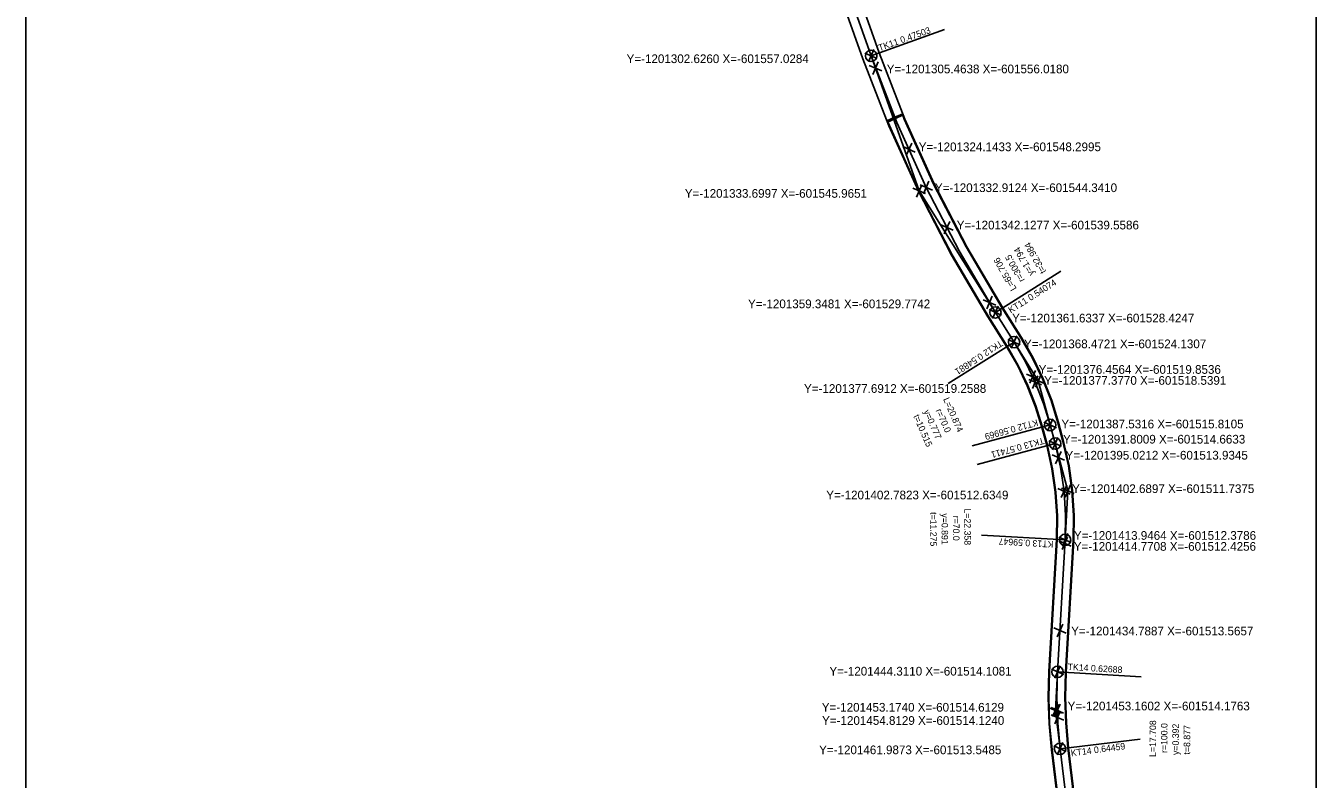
# Model space of a CAD drawing. Extents: x -601752 to -601455, y -1201912 to -1200862.
# Drawn here: x -601751.6 to -601454.6, y -1201469 to -1201295.7 of the extents above; entities that cross this region are included whole.
import ezdxf

# ---------------------------------------------------------------- set-up
doc = ezdxf.new("R2010")
doc.units = 0
for name, color, linetype in [('g_vytyceni oblouky', 7, 'Continuous'), ('g_vytyceni příčné', 7, 'Continuous'), ('u_návrh', 7, 'Continuous'), ('u_oblouky', 7, 'Continuous'), ('u_osa', 7, 'Continuous'), ('u_popis oblouky', 7, 'Continuous'), ('x_rám', 7, 'Continuous')]:
    doc.layers.add(name, color=color, linetype=linetype)

msp = doc.modelspace()

# ---------------------------------------------------------------- linework, layer by layer
at = {"layer": 'g_vytyceni oblouky'}
for p, q in [((-601558.46, -1201301.99), (-601555.6, -1201303.26)), ((-601556.4, -1201301.2), (-601557.66, -1201304.05)), ((-601545.33, -1201332.27), (-601546.6, -1201335.13)), ((-601545.77, -1201332.28), (-601542.91, -1201333.54)), ((-601543.71, -1201331.48), (-601544.97, -1201334.34)), ((-601547.39, -1201333.07), (-601544.54, -1201334.33)), ((-601529.85, -1201361), (-601527, -1201362.27)), ((-601527.79, -1201360.2), (-601529.06, -1201363.06)), ((-601525.56, -1201367.84), (-601522.7, -1201369.1)), ((-601523.5, -1201367.04), (-601524.76, -1201369.9)), ((-601519.97, -1201376.74), (-601517.11, -1201378.01)), ((-601518.63, -1201376.26), (-601519.89, -1201379.12)), ((-601517.91, -1201375.95), (-601519.17, -1201378.81)), ((-601520.69, -1201377.06), (-601517.83, -1201378.32)), ((-601517.24, -1201386.9), (-601514.38, -1201388.16)), ((-601515.18, -1201386.1), (-601516.44, -1201388.96)), ((-601516.09, -1201391.17), (-601513.23, -1201392.43)), ((-601514.03, -1201390.37), (-601515.3, -1201393.23)), ((-601514.06, -1201402.15), (-601511.21, -1201403.41)), ((-601512, -1201401.35), (-601513.27, -1201404.21)), ((-601513.17, -1201402.06), (-601510.31, -1201403.32)), ((-601511.1, -1201401.26), (-601512.37, -1201404.12)), ((-601511.75, -1201412.52), (-601513.01, -1201415.38)), ((-601513.81, -1201413.31), (-601510.95, -1201414.58)), ((-601515.54, -1201443.68), (-601512.68, -1201444.94)), ((-601513.48, -1201442.88), (-601514.74, -1201445.74)), ((-601516.04, -1201452.54), (-601513.18, -1201453.81)), ((-601515.61, -1201452.53), (-601512.75, -1201453.79)), ((-601513.98, -1201451.75), (-601515.25, -1201454.6)), ((-601513.54, -1201451.73), (-601514.81, -1201454.59)), ((-601514.98, -1201461.35), (-601512.12, -1201462.62)), ((-601512.92, -1201460.56), (-601514.18, -1201463.42))]:
    msp.add_line(p, q, dxfattribs=at)
at = {"layer": 'g_vytyceni příčné'}
for p, q in [((-601557.45, -1201304.83), (-601554.59, -1201306.1)), ((-601555.39, -1201304.04), (-601556.65, -1201306.89)), ((-601547.67, -1201322.71), (-601548.93, -1201325.57)), ((-601549.73, -1201323.51), (-601546.87, -1201324.78)), ((-601538.93, -1201340.7), (-601540.19, -1201343.56)), ((-601540.99, -1201341.5), (-601538.13, -1201342.76)), ((-601531.2, -1201358.72), (-601528.35, -1201359.98)), ((-601529.14, -1201357.92), (-601530.41, -1201360.78)), ((-601521.28, -1201375.82), (-601518.42, -1201377.09)), ((-601519.22, -1201375.03), (-601520.49, -1201377.89)), ((-601515.36, -1201394.39), (-601512.51, -1201395.65)), ((-601513.3, -1201393.59), (-601514.57, -1201396.45)), ((-601513.85, -1201414.14), (-601511, -1201415.4)), ((-601511.79, -1201413.34), (-601513.06, -1201416.2)), ((-601514.99, -1201434.16), (-601512.14, -1201435.42)), ((-601512.93, -1201433.36), (-601514.2, -1201436.22)), ((-601513.49, -1201453.38), (-601514.76, -1201456.24)), ((-601515.55, -1201454.18), (-601512.7, -1201455.45))]:
    msp.add_line(p, q, dxfattribs=at)
at = {"layer": 'u_návrh'}
for points in [[(-601563.54, -1201278.37), (-601555.15, -1201301.93), (-601549.25, -1201317.17), (-601542.54, -1201332.04), (-601535.03, -1201346.52), (-601526.72, -1201360.59), (-601522.42, -1201367.44), (-601519.75, -1201372.06), (-601517.42, -1201376.89), (-601515.46, -1201381.89), (-601513.89, -1201386.98), (-601512.72, -1201391.32), (-601511.46, -1201396.89), (-601510.64, -1201402.58), (-601510.28, -1201408.31), (-601510.38, -1201414.02), (-601512.11, -1201444.4), (-601512.27, -1201450.21), (-601512.09, -1201455.99), (-601511.56, -1201461.78), (-601506.35, -1201504.94)], [(-601567.28, -1201279.79), (-601558.9, -1201303.32), (-601552.94, -1201318.72), (-601546.14, -1201333.79), (-601538.53, -1201348.46), (-601530.13, -1201362.67), (-601525.84, -1201369.5), (-601523.29, -1201373.93), (-601521.09, -1201378.49), (-601519.24, -1201383.21), (-601517.73, -1201388.09), (-601516.61, -1201392.28), (-601515.4, -1201397.61), (-601514.63, -1201402.99), (-601514.28, -1201408.41), (-601514.38, -1201413.87), (-601516.11, -1201444.23), (-601516.27, -1201450.21), (-601516.08, -1201456.23), (-601515.54, -1201462.2), (-601510.32, -1201505.38)], [(-601549.72, -1201315.95), (-601551.7, -1201316.84), (-601553.38, -1201317.58)], [(-601549.62, -1201316.23), (-601551.59, -1201317.11), (-601553.27, -1201317.86)], [(-601549.75, -1201316.3), (-601549.39, -1201317.23), (-601542.68, -1201332.11), (-601535.16, -1201346.59), (-601526.84, -1201360.67), (-601522.55, -1201367.52), (-601519.89, -1201372.13), (-601517.56, -1201376.95), (-601515.6, -1201381.93), (-601514.03, -1201387.02), (-601512.87, -1201391.36), (-601511.61, -1201396.91), (-601510.79, -1201402.59), (-601510.43, -1201408.32), (-601510.53, -1201414.01), (-601512.26, -1201444.39), (-601512.42, -1201450.21), (-601512.24, -1201456), (-601511.71, -1201461.79), (-601506.5, -1201504.96), (-601506.06, -1201509.37), (-601505.82, -1201513.81), (-601505.77, -1201518.24), (-601506.19, -1201556.5)], [(-601553.14, -1201317.8), (-601552.81, -1201318.66), (-601546.01, -1201333.72), (-601538.39, -1201348.39), (-601530, -1201362.6), (-601525.72, -1201369.43), (-601523.16, -1201373.86), (-601520.96, -1201378.43), (-601519.1, -1201383.16), (-601517.59, -1201388.04), (-601516.46, -1201392.25), (-601515.25, -1201397.59), (-601514.48, -1201402.97), (-601514.13, -1201408.4), (-601514.23, -1201413.88), (-601515.96, -1201444.23), (-601516.12, -1201450.21), (-601515.93, -1201456.22), (-601515.39, -1201462.18), (-601510.17, -1201505.36), (-601509.75, -1201509.65), (-601509.52, -1201513.93), (-601509.47, -1201518.24), (-601509.71, -1201540.62)]]:
    msp.add_lwpolyline(points, dxfattribs=at)
at = {"layer": 'u_oblouky'}
for p, q in [((-601557.03, -1201302.63), (-601540.12, -1201296.61)), ((-601557.03, -1201302.63), (-601545.97, -1201333.7)), ((-601528.42, -1201361.63), (-601545.97, -1201333.7)), ((-601528.42, -1201361.63), (-601513.35, -1201352.17)), ((-601524.13, -1201368.47), (-601539.32, -1201378.01)), ((-601524.13, -1201368.47), (-601518.54, -1201377.38)), ((-601515.81, -1201387.53), (-601518.54, -1201377.38)), ((-601515.81, -1201387.53), (-601533.79, -1201392.36)), ((-601514.66, -1201391.8), (-601532.62, -1201396.62)), ((-601514.66, -1201391.8), (-601511.74, -1201402.69)), ((-601512.38, -1201413.95), (-601511.74, -1201402.69)), ((-601512.38, -1201413.95), (-601531.6, -1201412.85)), ((-601514.11, -1201444.31), (-601514.61, -1201453.17)), ((-601514.11, -1201444.31), (-601494.9, -1201445.41)), ((-601513.55, -1201461.99), (-601514.61, -1201453.17)), ((-601513.55, -1201461.99), (-601495.1, -1201459.76))]:
    msp.add_line(p, q, dxfattribs=at)
for centre in [(-601557.03, -1201302.63), (-601528.42, -1201361.63), (-601524.13, -1201368.47), (-601515.81, -1201387.53), (-601514.66, -1201391.8), (-601512.38, -1201413.95), (-601514.11, -1201444.31), (-601513.55, -1201461.99)]:
    msp.add_circle(centre, 1.31, dxfattribs=at)
at = {"layer": 'u_osa'}
msp.add_lwpolyline([(-601565.41, -1201279.08), (-601557.03, -1201302.63), (-601551.1, -1201317.94), (-601544.34, -1201332.91), (-601536.78, -1201347.49), (-601528.42, -1201361.63), (-601524.13, -1201368.47), (-601521.52, -1201372.99), (-601519.26, -1201377.69), (-601517.35, -1201382.55), (-601515.81, -1201387.53), (-601514.66, -1201391.8), (-601513.43, -1201397.25), (-601512.63, -1201402.78), (-601512.28, -1201408.36), (-601512.38, -1201413.95), (-601514.11, -1201444.31), (-601514.27, -1201450.21), (-601514.08, -1201456.11), (-601513.55, -1201461.99), (-601508.33, -1201505.16)], dxfattribs=at)
at = {"layer": 'x_rám'}
msp.add_lwpolyline([(-601454.58, -1200862.35), (-601454.58, -1201912.35), (-601751.58, -1201912.35), (-601751.58, -1200862.35)], close=True, dxfattribs=at)

# ---------------------------------------------------------------- texts
at = {"layer": 'g_vytyceni oblouky'}
for s, p in [('Y=-1201302.6260 X=-601557.0284', (-601613.31, -1201304.3)), ('Y=-1201332.9124 X=-601544.3410', (-601542.35, -1201333.96)), ('Y=-1201333.6997 X=-601545.9651', (-601599.91, -1201335.27)), ('Y=-1201361.6337 X=-601528.4247', (-601524.58, -1201363.94)), ('Y=-1201368.4721 X=-601524.1307', (-601521.83, -1201369.87)), ('Y=-1201377.3770 X=-601518.5391', (-601517.21, -1201378.28)), ('Y=-1201377.6912 X=-601519.2588', (-601572.47, -1201380.14)), ('Y=-1201387.5316 X=-601515.8105', (-601513.23, -1201388.3)), ('Y=-1201391.8009 X=-601514.6633', (-601512.85, -1201391.8)), ('Y=-1201402.7823 X=-601512.6349', (-601567.36, -1201404.63)), ('Y=-1201402.6897 X=-601511.7375', (-601510.76, -1201403.18)), ('Y=-1201413.9464 X=-601512.3786', (-601510.35, -1201413.93)), ('Y=-1201444.3110 X=-601514.1081', (-601566.62, -1201445.15)), ('Y=-1201453.1740 X=-601514.6129', (-601568.38, -1201453.45)), ('Y=-1201453.1602 X=-601514.1763', (-601511.8, -1201453.16)), ('Y=-1201461.9873 X=-601513.5485', (-601568.99, -1201463.24))]:
    msp.add_text(s, height=2, dxfattribs=at).set_placement(p)
at = {"layer": 'g_vytyceni příčné'}
for s, p in [('Y=-1201305.4638 X=-601556.0180', (-601553.43, -1201306.65)), ('Y=-1201324.1433 X=-601548.2995', (-601546.07, -1201324.56)), ('Y=-1201342.1277 X=-601539.5586', (-601537.32, -1201342.55)), ('Y=-1201359.3481 X=-601529.7742', (-601585.36, -1201360.67)), ('Y=-1201376.4564 X=-601519.8536', (-601518.46, -1201375.76)), ('Y=-1201395.0212 X=-601513.9345', (-601512.26, -1201395.48)), ('Y=-1201414.7708 X=-601512.4256', (-601510.37, -1201416.45)), ('Y=-1201434.7887 X=-601513.5657', (-601510.98, -1201435.91)), ('Y=-1201454.8129 X=-601514.1240', (-601568.31, -1201456.49))]:
    msp.add_text(s, height=2, dxfattribs=at).set_placement(p)
at = {"layer": 'u_oblouky'}
for s, rotation, p in [('y=1.794', 119.4465, (-601519.4, -1201352.71)), ('t=32.984', 119.4465, (-601516.67, -1201352.2)), ('L=65.706', 119.4465, (-601523.48, -1201356.17)), ('r=300.5', 119.4465, (-601521.6, -1201354.15)), ('L=20.874', 293.4563, (-601540.48, -1201381.59)), ('t=10.515', 293.4563, (-601547.36, -1201385.52)), ('y=0.777', 293.4563, (-601544.98, -1201384.39)), ('r=70.0', 293.4563, (-601542.21, -1201384.18)), ('t=11.275', 270, (-601543.43, -1201407.57)), ('y=0.891', 270, (-601540.81, -1201407.86)), ('r=70.0', 270, (-601538.18, -1201408.4)), ('L=22.358', 270, (-601535.56, -1201406.74)), ('L=17.708', 89.704, (-601491.47, -1201463.87)), ('r=100.0', 89.704, (-601488.84, -1201462.96)), ('y=0.392', 89.704, (-601486.22, -1201463.42)), ('t=8.877', 89.704, (-601483.6, -1201463.31))]:
    msp.add_text(s, height=1.5, rotation=rotation, dxfattribs=at).set_placement(p)
at = {"layer": 'u_popis oblouky'}
for s, rotation, p in [('TK11 0.47503', 19.5974, (-601555.06, -1201301.57)), ('KT11 0.54074', 32.1257, (-601524.88, -1201361.89)), ('TK12 0.54881', 213.2152, (-601527.37, -1201367.94)), ('KT12 0.56969', 195.4106, (-601518.86, -1201386.21)), ('TK13 0.57411', 195.401, (-601517.43, -1201390.39)), ('KT13 0.59647', 176.6841, (-601515.03, -1201414.26)), ('TK14 0.62688', 356.7401, (-601511.82, -1201443.87)), ('KT14 0.64459', 7.5366, (-601510.95, -1201463.74))]:
    msp.add_text(s, height=1.5, rotation=rotation, dxfattribs=at).set_placement(p)

doc.saveas('drawing.dxf')
